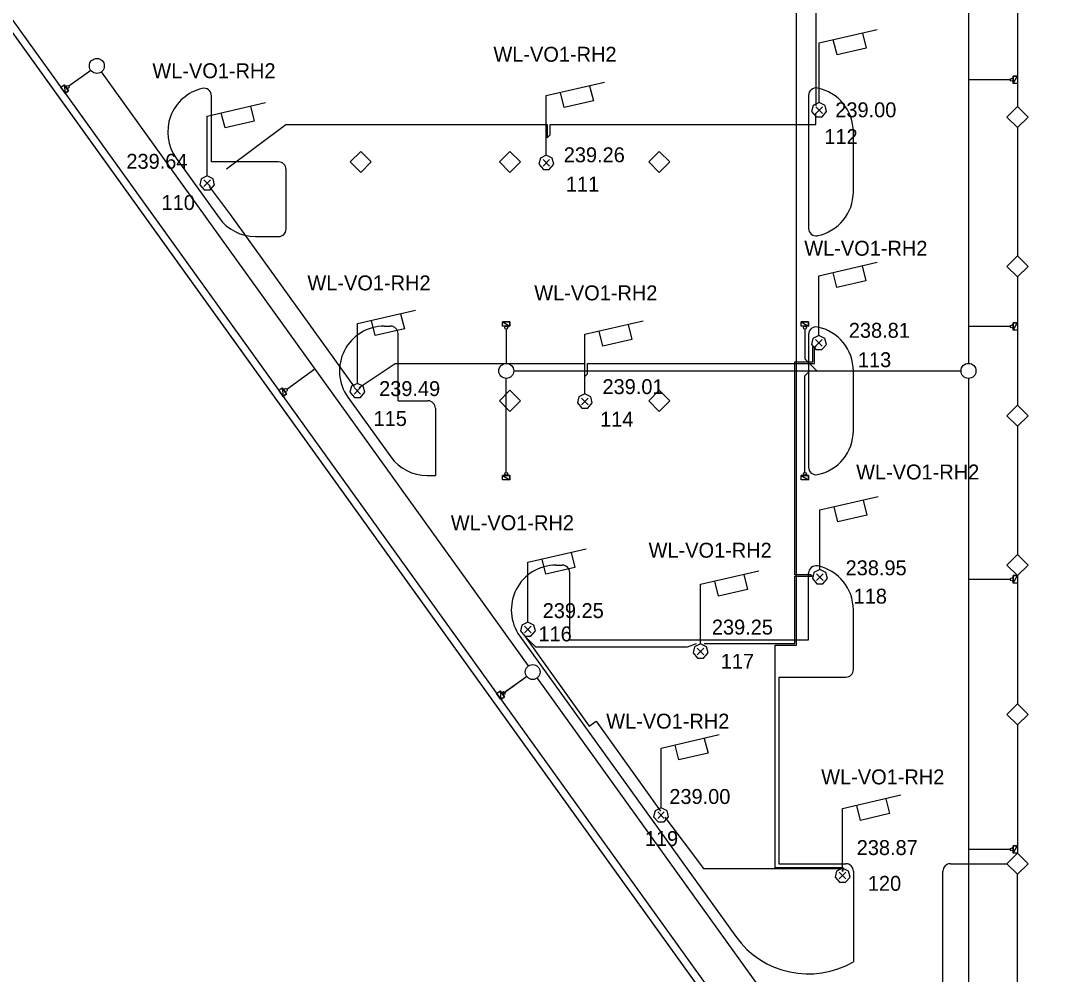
# Model space of a CAD drawing. Extents: x -264222 to -263592, y -1242345 to -1242048.
# Drawn here: x -264187.4 to -264118.8, y -1242277.9 to -1242214 of the extents above; entities that cross this region are included whole.
import ezdxf

# ---------------------------------------------------------------- set-up
doc = ezdxf.new("R2010")
doc.units = 0
for name, color, linetype in [('BOD_CISLO', 7, 'Continuous'), ('BOD_SYMBOL', 7, 'Continuous'), ('BOD_VYSKA', 7, 'Continuous'), ('KFA_2D_SITUACIA_DSP', 7, 'Continuous'), ('KFA_SO_62-1_VO_LAMPY_MERANE', 7, 'Continuous'), ('KFA_SO_62-1_VO_POPIS_LAMP_PROJEKT', 7, 'Continuous'), ('KFA_SO_62-1_VO_TRASA_KABLOV_PROJEKT', 7, 'Continuous')]:
    doc.layers.add(name, color=color, linetype=linetype)

msp = doc.modelspace()

# ---------------------------------------------------------------- linework, layer by layer
at = {"layer": 'BOD_SYMBOL'}
for p, q in [((-264134.083, -1242220.231), (-264133.641, -1242219.789)), ((-264133.641, -1242220.231), (-264134.083, -1242219.789)), ((-264152.355, -1242223.762), (-264151.913, -1242223.32)), ((-264151.913, -1242223.762), (-264152.355, -1242223.32)), ((-264175.076, -1242225.131), (-264174.634, -1242224.689)), ((-264174.634, -1242225.131), (-264175.076, -1242224.689)), ((-264134.095, -1242235.823), (-264133.653, -1242235.381)), ((-264133.653, -1242235.823), (-264134.095, -1242235.381)), ((-264165.013, -1242239.032), (-264164.571, -1242238.59)), ((-264164.571, -1242239.032), (-264165.013, -1242238.59)), ((-264149.773, -1242239.741), (-264149.331, -1242239.299)), ((-264149.331, -1242239.741), (-264149.773, -1242239.299)), ((-264134.03, -1242251.503), (-264133.588, -1242251.061)), ((-264133.588, -1242251.503), (-264134.03, -1242251.061)), ((-264153.587, -1242255.016), (-264153.145, -1242254.574)), ((-264153.145, -1242255.016), (-264153.587, -1242254.574)), ((-264142.019, -1242256.483), (-264141.577, -1242256.041)), ((-264141.577, -1242256.483), (-264142.019, -1242256.041)), ((-264144.671, -1242267.455), (-264144.229, -1242267.013)), ((-264144.229, -1242267.455), (-264144.671, -1242267.013)), ((-264132.511, -1242271.497), (-264132.069, -1242271.055)), ((-264132.069, -1242271.497), (-264132.511, -1242271.055))]:
    msp.add_line(p, q, dxfattribs=at)
at = {"layer": 'KFA_2D_SITUACIA_DSP'}
for p, q in [((-264204.694, -1242191.482), (-264115.871, -1242314.982)), ((-264204.078, -1242191.482), (-264119.75, -1242308.732)), ((-264123.854, -1242207), (-264123.854, -1242236.976)), ((-264120.568, -1242211.189), (-264120.568, -1242219.774)), ((-264184.115, -1242218.399), (-264182.649, -1242217.344)), ((-264181.951, -1242217.458), (-264153.34, -1242257.238)), ((-264120.86, -1242218.232), (-264120.86, -1242217.732)), ((-264120.86, -1242217.732), (-264120.57, -1242217.732)), ((-264120.86, -1242218.232), (-264120.57, -1242217.732)), ((-264120.86, -1242218.232), (-264120.57, -1242217.732)), ((-264120.57, -1242217.732), (-264120.86, -1242217.732)), ((-264120.86, -1242217.732), (-264120.86, -1242218.232)), ((-264120.57, -1242217.732), (-264120.57, -1242218.232)), ((-264184.659, -1242218.482), (-264184.424, -1242218.313)), ((-264184.367, -1242218.888), (-264184.659, -1242218.482)), ((-264184.424, -1242218.313), (-264184.132, -1242218.719)), ((-264184.424, -1242218.313), (-264184.367, -1242218.888)), ((-264184.424, -1242218.313), (-264184.367, -1242218.888)), ((-264184.132, -1242218.719), (-264184.424, -1242218.313)), ((-264121.058, -1242217.982), (-264123.854, -1242217.982)), ((-264120.57, -1242218.232), (-264120.86, -1242218.232)), ((-264184.132, -1242218.719), (-264184.367, -1242218.888)), ((-264184.367, -1242218.888), (-264184.132, -1242218.719)), ((-264134.568, -1242219.033), (-264134.568, -1242227.932)), ((-264120.568, -1242221.189), (-264120.568, -1242229.774)), ((-264131.568, -1242225.482), (-264131.568, -1242221.482)), ((-264176.93, -1242223.234), (-264174.054, -1242227.234)), ((-264169.568, -1242227.982), (-264169.568, -1242223.982)), ((-264171.618, -1242228.482), (-264170.068, -1242228.482)), ((-264120.568, -1242231.189), (-264120.568, -1242239.774)), ((-264155.068, -1242234.192), (-264154.568, -1242234.192)), ((-264155.068, -1242234.482), (-264155.068, -1242234.192)), ((-264155.068, -1242234.192), (-264154.568, -1242234.482)), ((-264155.068, -1242234.192), (-264154.568, -1242234.482)), ((-264154.568, -1242234.192), (-264155.068, -1242234.192)), ((-264154.568, -1242234.192), (-264154.568, -1242234.482)), ((-264154.568, -1242234.482), (-264154.568, -1242234.192)), ((-264135.061, -1242234.192), (-264134.561, -1242234.192)), ((-264135.061, -1242234.482), (-264135.061, -1242234.192)), ((-264135.061, -1242234.192), (-264134.561, -1242234.482)), ((-264135.061, -1242234.192), (-264134.561, -1242234.482)), ((-264134.561, -1242234.192), (-264135.061, -1242234.192)), ((-264134.561, -1242234.192), (-264134.561, -1242234.482)), ((-264134.561, -1242234.482), (-264134.561, -1242234.192)), ((-264120.858, -1242234.749), (-264120.858, -1242234.249)), ((-264120.858, -1242234.249), (-264120.568, -1242234.249)), ((-264120.858, -1242234.749), (-264120.568, -1242234.249)), ((-264120.858, -1242234.749), (-264120.568, -1242234.249)), ((-264120.568, -1242234.249), (-264120.858, -1242234.249)), ((-264120.858, -1242234.249), (-264120.858, -1242234.749)), ((-264120.568, -1242234.249), (-264120.568, -1242234.749)), ((-264162.988, -1242234.482), (-264162.568, -1242234.482)), ((-264162.068, -1242239.482), (-264162.068, -1242234.982)), ((-264154.568, -1242234.482), (-264155.068, -1242234.482)), ((-264154.818, -1242234.682), (-264154.818, -1242236.976)), ((-264134.561, -1242234.482), (-264135.061, -1242234.482)), ((-264134.811, -1242234.682), (-264134.811, -1242236.68)), ((-264121.058, -1242234.499), (-264123.854, -1242234.499)), ((-264120.568, -1242234.749), (-264120.858, -1242234.749)), ((-264134.568, -1242235.033), (-264134.568, -1242243.932)), ((-264134.811, -1242236.68), (-264134.016, -1242237.476)), ((-264169.518, -1242238.695), (-264167.646, -1242237.348)), ((-264154.318, -1242237.476), (-264124.354, -1242237.476)), ((-264134.811, -1242237.801), (-264134.486, -1242237.476)), ((-264131.568, -1242241.482), (-264131.568, -1242237.482)), ((-264154.824, -1242244.276), (-264154.824, -1242237.976)), ((-264134.811, -1242244.276), (-264134.811, -1242237.801)), ((-264123.854, -1242237.976), (-264123.854, -1242297.736)), ((-264170.062, -1242238.778), (-264169.827, -1242238.609)), ((-264169.77, -1242239.184), (-264170.062, -1242238.778)), ((-264169.827, -1242238.609), (-264169.535, -1242239.015)), ((-264169.827, -1242238.609), (-264169.77, -1242239.184)), ((-264169.827, -1242238.609), (-264169.77, -1242239.184)), ((-264169.535, -1242239.015), (-264169.827, -1242238.609)), ((-264169.535, -1242239.015), (-264169.77, -1242239.184)), ((-264169.77, -1242239.184), (-264169.535, -1242239.015)), ((-264165.423, -1242239.234), (-264162.546, -1242243.234)), ((-264162.068, -1242239.482), (-264160.068, -1242239.482)), ((-264159.568, -1242239.982), (-264159.568, -1242244.482)), ((-264120.568, -1242241.189), (-264120.568, -1242249.774)), ((-264160.111, -1242244.482), (-264159.568, -1242244.482)), ((-264155.074, -1242244.476), (-264154.574, -1242244.476)), ((-264155.074, -1242244.766), (-264155.074, -1242244.476)), ((-264155.074, -1242244.476), (-264154.574, -1242244.766)), ((-264155.074, -1242244.476), (-264154.574, -1242244.766)), ((-264154.574, -1242244.476), (-264155.074, -1242244.476)), ((-264154.574, -1242244.476), (-264154.574, -1242244.766)), ((-264154.574, -1242244.766), (-264154.574, -1242244.476)), ((-264135.068, -1242244.476), (-264134.568, -1242244.476)), ((-264135.068, -1242244.766), (-264135.068, -1242244.476)), ((-264135.068, -1242244.476), (-264134.568, -1242244.766)), ((-264135.068, -1242244.476), (-264134.568, -1242244.766)), ((-264134.568, -1242244.476), (-264135.068, -1242244.476)), ((-264134.568, -1242244.476), (-264134.568, -1242244.766)), ((-264134.568, -1242244.766), (-264134.568, -1242244.476)), ((-264154.574, -1242244.766), (-264155.074, -1242244.766)), ((-264134.568, -1242244.766), (-264135.068, -1242244.766)), ((-264151.48, -1242250.482), (-264151.068, -1242250.482)), ((-264150.568, -1242255.482), (-264150.568, -1242250.982)), ((-264134.568, -1242255.482), (-264134.568, -1242251.033)), ((-264121.057, -1242251.439), (-264123.853, -1242251.439)), ((-264120.857, -1242251.689), (-264120.857, -1242251.189)), ((-264120.857, -1242251.189), (-264120.567, -1242251.189)), ((-264120.857, -1242251.689), (-264120.567, -1242251.189)), ((-264120.857, -1242251.689), (-264120.567, -1242251.189)), ((-264120.567, -1242251.189), (-264120.857, -1242251.189)), ((-264120.857, -1242251.189), (-264120.857, -1242251.689)), ((-264120.568, -1242251.191), (-264120.568, -1242259.775)), ((-264120.567, -1242251.189), (-264120.567, -1242251.689)), ((-264120.567, -1242251.689), (-264120.857, -1242251.689)), ((-264131.568, -1242257.482), (-264131.568, -1242253.482)), ((-264153.916, -1242255.234), (-264139.439, -1242275.363)), ((-264150.568, -1242255.482), (-264134.568, -1242255.482)), ((-264155.084, -1242259.108), (-264153.454, -1242257.936)), ((-264154.921, -1242258.991), (-264153.454, -1242257.936)), ((-264152.757, -1242258.05), (-264124.146, -1242297.83)), ((-264152.757, -1242258.05), (-264124.146, -1242297.83)), ((-264136.568, -1242257.982), (-264136.568, -1242270.482)), ((-264136.568, -1242257.982), (-264132.068, -1242257.982)), ((-264155.465, -1242259.074), (-264155.23, -1242258.905)), ((-264155.23, -1242258.905), (-264154.938, -1242259.311)), ((-264155.23, -1242258.905), (-264155.173, -1242259.48)), ((-264155.23, -1242258.905), (-264155.173, -1242259.48)), ((-264154.938, -1242259.311), (-264155.23, -1242258.905)), ((-264155.173, -1242259.48), (-264155.465, -1242259.074)), ((-264154.938, -1242259.311), (-264155.173, -1242259.48)), ((-264155.173, -1242259.48), (-264154.938, -1242259.311)), ((-264120.568, -1242261.189), (-264120.568, -1242269.774)), ((-264120.857, -1242269.775), (-264120.857, -1242269.275)), ((-264120.857, -1242269.275), (-264120.567, -1242269.275)), ((-264120.857, -1242269.775), (-264120.567, -1242269.275)), ((-264120.857, -1242269.775), (-264120.567, -1242269.275)), ((-264120.567, -1242269.275), (-264120.857, -1242269.275)), ((-264120.857, -1242269.275), (-264120.857, -1242269.775)), ((-264120.567, -1242269.275), (-264120.567, -1242269.775)), ((-264121.058, -1242269.525), (-264123.854, -1242269.525)), ((-264120.567, -1242269.775), (-264120.857, -1242269.775)), ((-264136.568, -1242270.482), (-264132.068, -1242270.482)), ((-264125.068, -1242270.482), (-264121.275, -1242270.482)), ((-264131.568, -1242270.982), (-264131.568, -1242277.056)), ((-264125.568, -1242287.467), (-264125.568, -1242270.982))]:
    msp.add_line(p, q, dxfattribs=at)
for points in [[(-264204.694, -1242191.482), (-264137.78, -1242284.52), (-264125.581, -1242301.482)], [(-264170.068, -1242223.482), (-264174.568, -1242223.482), (-264174.568, -1242219.049)], [(-264120.568, -1242296.035), (-264120.568, -1242271.189), (-264120.568, -1242271.189)]]:
    msp.add_lwpolyline(points, dxfattribs=at)
for points in [[(-264120.568, -1242219.775), (-264119.861, -1242220.482), (-264120.568, -1242221.189), (-264121.275, -1242220.482)], [(-264163.861, -1242223.482), (-264164.568, -1242222.775), (-264165.275, -1242223.482), (-264164.568, -1242224.189)], [(-264153.861, -1242223.482), (-264154.568, -1242222.775), (-264155.275, -1242223.482), (-264154.568, -1242224.189)], [(-264143.861, -1242223.482), (-264144.568, -1242222.775), (-264145.275, -1242223.482), (-264144.568, -1242224.189)], [(-264120.568, -1242229.775), (-264119.861, -1242230.482), (-264120.568, -1242231.189), (-264121.275, -1242230.482)], [(-264153.861, -1242239.482), (-264154.568, -1242238.775), (-264155.275, -1242239.482), (-264154.568, -1242240.189)], [(-264143.861, -1242239.482), (-264144.568, -1242238.775), (-264145.275, -1242239.482), (-264144.568, -1242240.189)], [(-264120.568, -1242239.775), (-264119.861, -1242240.482), (-264120.568, -1242241.189), (-264121.275, -1242240.482)], [(-264120.568, -1242249.775), (-264119.861, -1242250.482), (-264120.568, -1242251.189), (-264121.275, -1242250.482)], [(-264120.568, -1242259.775), (-264119.861, -1242260.482), (-264120.568, -1242261.189), (-264121.275, -1242260.482)], [(-264120.568, -1242269.775), (-264119.861, -1242270.482), (-264120.568, -1242271.189), (-264121.275, -1242270.482)]]:
    msp.add_lwpolyline(points, close=True, dxfattribs=at)
for centre, radius in [((-264182.243, -1242217.052), 0.5), ((-264184.194, -1242218.461), 0.1), ((-264120.958, -1242217.982), 0.1), ((-264154.818, -1242234.582), 0.1), ((-264134.811, -1242234.582), 0.1), ((-264120.958, -1242234.499), 0.1), ((-264154.818, -1242237.476), 0.5), ((-264123.854, -1242237.476), 0.5), ((-264169.597, -1242238.757), 0.1), ((-264154.818, -1242244.376), 0.1), ((-264134.811, -1242244.376), 0.1), ((-264120.957, -1242251.439), 0.1), ((-264153.049, -1242257.644), 0.5), ((-264155, -1242259.053), 0.1), ((-264120.958, -1242269.525), 0.1)]:
    msp.add_circle(centre, radius, dxfattribs=at)
for centre, radius, start, end in [((-264175.068, -1242219.049), 0.5, 0, 103.24756), ((-264134.068, -1242219.033), 0.5, 78.46304, 180), ((-264134.568, -1242221.482), 3, 0, 78.46304), ((-264174.495, -1242221.482), 3, 103.24756, 215.72401), ((-264170.068, -1242223.982), 0.5, 0, 90), ((-264134.568, -1242225.482), 3, 281.53696, 0), ((-264171.618, -1242225.482), 3, 215.72401, 270), ((-264170.068, -1242227.982), 0.5, 270, 0), ((-264134.068, -1242227.932), 0.5, 180, 281.53696), ((-264162.988, -1242237.482), 3, 90, 215.72401), ((-264162.568, -1242234.982), 0.5, 0, 90), ((-264134.068, -1242235.033), 0.5, 78.46304, 180), ((-264134.568, -1242237.482), 3, 0, 78.46304), ((-264160.068, -1242239.982), 0.5, 0, 90), ((-264134.568, -1242241.482), 3, 281.53696, 0), ((-264160.111, -1242241.482), 3, 215.72401, 270), ((-264134.068, -1242243.932), 0.5, 180, 281.53696), ((-264151.48, -1242253.482), 3, 90, 215.72401), ((-264151.068, -1242250.982), 0.5, 0, 90), ((-264134.068, -1242251.033), 0.5, 78.46304, 180), ((-264134.568, -1242253.482), 3, 0, 78.46304), ((-264132.068, -1242257.482), 0.5, 270, 0), ((-264132.068, -1242270.982), 0.5, 0, 90), ((-264125.068, -1242270.982), 0.5, 90, 180), ((-264134.568, -1242271.86), 6, 215.72401, 300)]:
    msp.add_arc(centre, radius, start, end, dxfattribs=at)
at = {"layer": 'KFA_SO_62-1_VO_LAMPY_MERANE'}
for p, q in [((-264133.912, -1242220.01), (-264133.812, -1242220.01)), ((-264133.862, -1242220.01), (-264133.862, -1242220.01)), ((-264152.184, -1242223.541), (-264152.084, -1242223.541)), ((-264152.134, -1242223.541), (-264152.134, -1242223.541)), ((-264174.905, -1242224.91), (-264174.805, -1242224.91)), ((-264174.855, -1242224.91), (-264174.855, -1242224.91)), ((-264133.924, -1242235.602), (-264133.824, -1242235.602)), ((-264133.874, -1242235.602), (-264133.874, -1242235.602)), ((-264164.842, -1242238.811), (-264164.742, -1242238.811)), ((-264164.792, -1242238.811), (-264164.792, -1242238.811)), ((-264149.602, -1242239.52), (-264149.502, -1242239.52)), ((-264149.552, -1242239.52), (-264149.552, -1242239.52)), ((-264133.859, -1242251.282), (-264133.759, -1242251.282)), ((-264133.809, -1242251.282), (-264133.809, -1242251.282)), ((-264153.416, -1242254.795), (-264153.316, -1242254.795)), ((-264153.366, -1242254.795), (-264153.366, -1242254.795)), ((-264141.848, -1242256.262), (-264141.748, -1242256.262)), ((-264141.798, -1242256.262), (-264141.798, -1242256.262)), ((-264144.5, -1242267.234), (-264144.4, -1242267.234)), ((-264144.45, -1242267.234), (-264144.45, -1242267.234)), ((-264132.34, -1242271.276), (-264132.24, -1242271.276)), ((-264132.29, -1242271.276), (-264132.29, -1242271.276))]:
    msp.add_line(p, q, dxfattribs=at)
for points in [[(-264133.862, -1242219.51), (-264134.262, -1242219.71), (-264134.362, -1242220.11), (-264134.062, -1242220.46), (-264133.662, -1242220.46), (-264133.362, -1242220.11), (-264133.462, -1242219.71), (-264133.862, -1242219.51), (-264133.862, -1242215.51), (-264129.962, -1242214.61)], [(-264130.962, -1242214.86), (-264130.712, -1242215.86), (-264132.662, -1242216.31), (-264132.912, -1242215.31)], [(-264152.134, -1242223.041), (-264152.534, -1242223.241), (-264152.634, -1242223.641), (-264152.334, -1242223.991), (-264151.934, -1242223.991), (-264151.634, -1242223.641), (-264151.734, -1242223.241), (-264152.134, -1242223.041), (-264152.134, -1242219.041), (-264148.234, -1242218.141)], [(-264149.234, -1242218.391), (-264148.984, -1242219.391), (-264150.934, -1242219.841), (-264151.184, -1242218.841)], [(-264174.855, -1242224.41), (-264175.255, -1242224.61), (-264175.355, -1242225.01), (-264175.055, -1242225.36), (-264174.655, -1242225.36), (-264174.355, -1242225.01), (-264174.455, -1242224.61), (-264174.855, -1242224.41), (-264174.855, -1242220.41), (-264170.955, -1242219.51)], [(-264171.955, -1242219.76), (-264171.705, -1242220.76), (-264173.655, -1242221.21), (-264173.905, -1242220.21)], [(-264133.874, -1242235.102), (-264134.274, -1242235.302), (-264134.374, -1242235.702), (-264134.074, -1242236.052), (-264133.674, -1242236.052), (-264133.374, -1242235.702), (-264133.474, -1242235.302), (-264133.874, -1242235.102), (-264133.874, -1242231.102), (-264129.974, -1242230.202)], [(-264130.974, -1242230.452), (-264130.724, -1242231.452), (-264132.674, -1242231.902), (-264132.924, -1242230.902)], [(-264164.792, -1242238.311), (-264165.192, -1242238.511), (-264165.292, -1242238.911), (-264164.992, -1242239.261), (-264164.592, -1242239.261), (-264164.292, -1242238.911), (-264164.392, -1242238.511), (-264164.792, -1242238.311), (-264164.792, -1242234.311), (-264160.892, -1242233.411)], [(-264161.892, -1242233.661), (-264161.642, -1242234.661), (-264163.592, -1242235.111), (-264163.842, -1242234.111)], [(-264149.552, -1242239.02), (-264149.952, -1242239.22), (-264150.052, -1242239.62), (-264149.752, -1242239.97), (-264149.352, -1242239.97), (-264149.052, -1242239.62), (-264149.152, -1242239.22), (-264149.552, -1242239.02), (-264149.552, -1242235.02), (-264145.652, -1242234.12)], [(-264146.652, -1242234.37), (-264146.402, -1242235.37), (-264148.352, -1242235.82), (-264148.602, -1242234.82)], [(-264133.809, -1242250.782), (-264134.209, -1242250.982), (-264134.309, -1242251.382), (-264134.009, -1242251.732), (-264133.609, -1242251.732), (-264133.309, -1242251.382), (-264133.409, -1242250.982), (-264133.809, -1242250.782), (-264133.809, -1242246.782), (-264129.909, -1242245.882)], [(-264130.909, -1242246.132), (-264130.659, -1242247.132), (-264132.609, -1242247.582), (-264132.859, -1242246.582)], [(-264153.366, -1242254.295), (-264153.766, -1242254.495), (-264153.866, -1242254.895), (-264153.566, -1242255.245), (-264153.166, -1242255.245), (-264152.866, -1242254.895), (-264152.966, -1242254.495), (-264153.366, -1242254.295), (-264153.366, -1242250.295), (-264149.466, -1242249.395)], [(-264150.466, -1242249.645), (-264150.216, -1242250.645), (-264152.166, -1242251.095), (-264152.416, -1242250.095)], [(-264141.798, -1242255.762), (-264142.198, -1242255.962), (-264142.298, -1242256.362), (-264141.998, -1242256.712), (-264141.598, -1242256.712), (-264141.298, -1242256.362), (-264141.398, -1242255.962), (-264141.798, -1242255.762), (-264141.798, -1242251.762), (-264137.898, -1242250.862)], [(-264138.898, -1242251.112), (-264138.648, -1242252.112), (-264140.598, -1242252.562), (-264140.848, -1242251.562)], [(-264144.45, -1242266.734), (-264144.85, -1242266.934), (-264144.95, -1242267.334), (-264144.65, -1242267.684), (-264144.25, -1242267.684), (-264143.95, -1242267.334), (-264144.05, -1242266.934), (-264144.45, -1242266.734), (-264144.45, -1242262.734), (-264140.55, -1242261.834)], [(-264141.55, -1242262.084), (-264141.3, -1242263.084), (-264143.25, -1242263.534), (-264143.5, -1242262.534)], [(-264132.29, -1242270.776), (-264132.69, -1242270.976), (-264132.79, -1242271.376), (-264132.49, -1242271.726), (-264132.09, -1242271.726), (-264131.79, -1242271.376), (-264131.89, -1242270.976), (-264132.29, -1242270.776), (-264132.29, -1242266.776), (-264128.39, -1242265.876)], [(-264129.39, -1242266.126), (-264129.14, -1242267.126), (-264131.09, -1242267.576), (-264131.34, -1242266.576)]]:
    msp.add_lwpolyline(points, dxfattribs=at)
at = {"layer": 'KFA_SO_62-1_VO_TRASA_KABLOV_PROJEKT'}
for p, q in [((-264135.375, -1242250.669), (-264135.36, -1242193.1)), ((-264134.075, -1242204.292), (-264134.075, -1242219.722)), ((-264134.08, -1242220.982), (-264134.075, -1242220.222)), ((-264173.55, -1242223.95), (-264169.586, -1242220.982)), ((-264169.586, -1242220.982), (-264152.068, -1242220.982)), ((-264152.068, -1242220.982), (-264152.068, -1242221.873)), ((-264151.874, -1242221.679), (-264151.874, -1242220.982)), ((-264151.874, -1242220.982), (-264134.08, -1242220.982)), ((-264152.068, -1242221.873), (-264151.874, -1242221.679)), ((-264174.722, -1242225.124), (-264173.313, -1242227)), ((-264173.313, -1242227), (-264165.016, -1242238.534)), ((-264134.279, -1242235.885), (-264134.066, -1242235.825)), ((-264134.279, -1242236.878), (-264134.279, -1242235.885)), ((-264134.171, -1242235.943), (-264134.066, -1242235.825)), ((-264134.171, -1242236.984), (-264134.171, -1242235.943)), ((-264164.667, -1242238.591), (-264162.252, -1242236.984)), ((-264162.252, -1242236.984), (-264149.568, -1242236.984)), ((-264149.568, -1242236.984), (-264149.568, -1242237.876)), ((-264149.368, -1242237.676), (-264149.368, -1242236.984)), ((-264149.368, -1242236.984), (-264134.171, -1242236.984)), ((-264135.478, -1242251.124), (-264135.478, -1242236.878)), ((-264135.478, -1242236.878), (-264134.279, -1242236.878)), ((-264149.568, -1242237.876), (-264149.368, -1242237.676)), ((-264135.375, -1242255.85), (-264135.375, -1242250.669)), ((-264135.48, -1242251.23), (-264134.32, -1242251.222)), ((-264135.48, -1242255.737), (-264135.48, -1242251.23)), ((-264134.429, -1242251.124), (-264135.478, -1242251.124)), ((-264134.32, -1242251.222), (-264134.429, -1242251.124)), ((-264153.577, -1242255.25), (-264149.253, -1242261.263)), ((-264153.577, -1242255.25), (-264152.87, -1242255.96)), ((-264152.87, -1242255.96), (-264142.68, -1242255.96)), ((-264142.68, -1242255.96), (-264142.063, -1242255.737)), ((-264141.563, -1242255.737), (-264135.48, -1242255.737)), ((-264136.795, -1242270.75), (-264136.795, -1242255.85)), ((-264136.795, -1242255.85), (-264135.375, -1242255.85)), ((-264149.253, -1242261.263), (-264148.806, -1242260.941)), ((-264148.806, -1242260.941), (-264144.481, -1242266.954)), ((-264144.189, -1242267.36), (-264141.595, -1242270.8)), ((-264141.595, -1242270.8), (-264132.313, -1242270.8)), ((-264132.245, -1242270.75), (-264136.795, -1242270.75)), ((-264132.313, -1242270.8), (-264132.313, -1242270.982)), ((-264132.313, -1242270.982), (-264132.245, -1242270.95)), ((-264132.245, -1242270.95), (-264132.245, -1242270.75))]:
    msp.add_line(p, q, dxfattribs=at)

# ---------------------------------------------------------------- texts
at = {"layer": 'BOD_CISLO'}
for s, p in [('112', (-264133.51, -1242222.287)), ('111', (-264150.826, -1242225.468)), ('110', (-264177.907, -1242226.702)), ('113', (-264131.262, -1242237.23)), ('115', (-264163.706, -1242241.167)), ('114', (-264148.533, -1242241.212)), ('118', (-264131.549, -1242253.063)), ('116', (-264152.662, -1242255.59)), ('117', (-264140.448, -1242257.426)), ('119', (-264145.536, -1242269.299)), ('120', (-264130.596, -1242272.296))]:
    msp.add_text(s, height=1, dxfattribs=at).set_placement(p)
at = {"layer": 'BOD_VYSKA'}
for s, p in [('239.00', (-264132.777, -1242220.495)), ('239.26', (-264150.967, -1242223.507)), ('239.64', (-264180.264, -1242223.943)), ('238.81', (-264131.871, -1242235.262)), ('239.49', (-264163.334, -1242239.163)), ('239.01', (-264148.372, -1242239.033)), ('238.95', (-264132.087, -1242251.165)), ('239.25', (-264152.377, -1242254.031)), ('239.25', (-264141.044, -1242255.134)), ('239.00', (-264143.894, -1242266.479)), ('238.87', (-264131.342, -1242269.9))]:
    msp.add_text(s, height=1, dxfattribs=at).set_placement(p)
at = {"layer": 'KFA_SO_62-1_VO_POPIS_LAMP_PROJEKT'}
for p in [(-264155.676, -1242216.775), (-264178.522, -1242217.876), (-264134.853, -1242229.765), (-264168.137, -1242232.085), (-264152.941, -1242232.753), (-264131.38, -1242244.748), (-264158.532, -1242248.146), (-264145.281, -1242249.987), (-264148.121, -1242261.434), (-264133.72, -1242265.166)]:
    msp.add_text('WL-VO1-RH2', height=1, dxfattribs=at).set_placement(p)

doc.saveas('drawing.dxf')
